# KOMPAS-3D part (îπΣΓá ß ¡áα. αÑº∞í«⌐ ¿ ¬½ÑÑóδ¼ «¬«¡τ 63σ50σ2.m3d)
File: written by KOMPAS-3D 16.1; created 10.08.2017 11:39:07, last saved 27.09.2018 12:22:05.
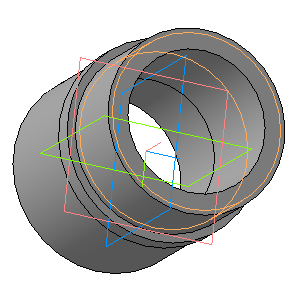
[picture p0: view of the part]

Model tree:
1. Эскиз:1
2. Операция вращения:1
     Угол 1 = 360
3. Условное изображение резьбы:3  (labels: G 2)
     Длина резьбы = 25.7; Шаг резьбы = 2.309; Номинальный диаметр резьбы = 59.614
4. Подгонка:2  (labels: Муфта с нар. резьбой и клеевым оконч 63х50х2)

Referenced files in C:\Program Files\ASCON\KOMPAS-3D V16\Sys\Thread\: cil2_6357-81.xml
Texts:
  Линейный размер с обрывом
